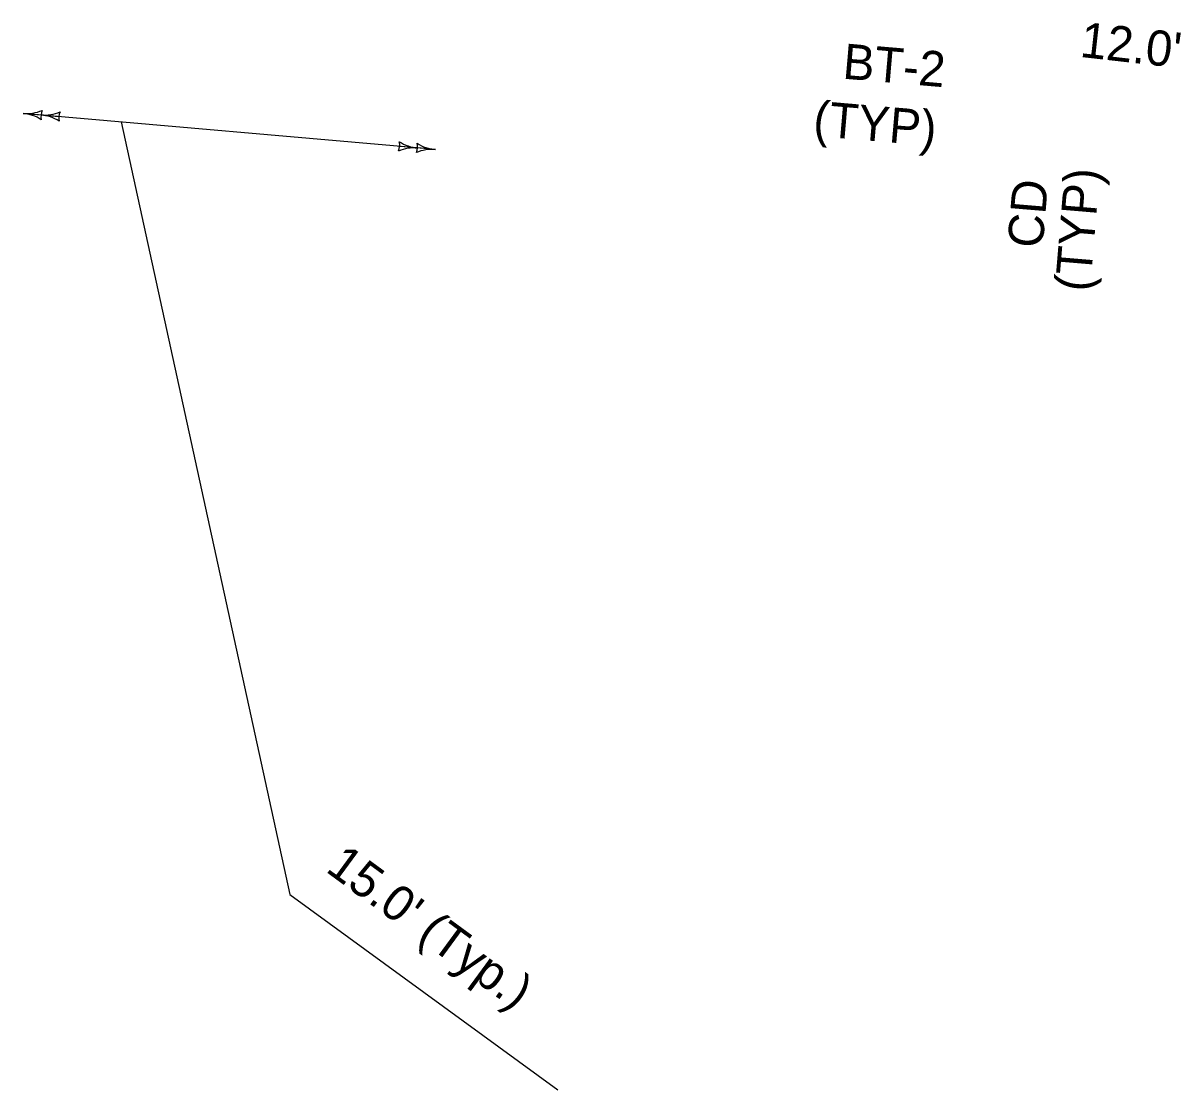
# Model space of a CAD drawing. Extents: x 15567221 to 15568484, y 8782768 to 8783889.
# Drawn here: x 15567891.2 to 15567953.3, y 8782767.6 to 8782824.8 of the extents above; entities that cross this region are included whole.
import ezdxf

# ---------------------------------------------------------------- set-up
doc = ezdxf.new("R2010")
doc.units = 0
for name, color, linetype in [('Default', 7, 'Continuous'), ('Drainage', 7, 'Continuous'), ('EXT_GU', 7, 'Continuous')]:
    doc.layers.add(name, color=color, linetype=linetype)

msp = doc.modelspace()

# ---------------------------------------------------------------- linework, layer by layer
at = {"layer": 'Drainage'}
for p, q in [((15567913.327, 8782817.986), (15567891.234, 8782819.924)), ((15567896.482, 8782819.464), (15567905.529, 8782778.036)), ((15567905.529, 8782778.036), (15567919.884, 8782767.57))]:
    msp.add_line(p, q, dxfattribs=at)
at = {"layer": 'EXT_GU'}
for p, q in [((15567891.234, 8782819.924), (15567891.717, 8782819.882)), ((15567891.234, 8782819.924), (15567892.191, 8782819.84)), ((15567892.191, 8782819.84), (15567892.674, 8782819.798)), ((15567892.191, 8782819.84), (15567893.149, 8782819.756)), ((15567912.369, 8782818.07), (15567911.412, 8782818.154)), ((15567912.369, 8782818.07), (15567911.887, 8782818.113)), ((15567913.327, 8782817.986), (15567912.369, 8782818.07)), ((15567913.327, 8782817.986), (15567912.844, 8782818.029))]:
    msp.add_line(p, q, dxfattribs=at)
for centre, radius, start, end in [((15567891.42, 8782822.041), 2.125, 264.98723, 293.05972), ((15567891.048, 8782817.807), 2.125, 56.91474, 84.98723), ((15567893.009, 8782819.768), 0.821, 157.25388, 192.72058), ((15567892.377, 8782821.957), 2.125, 264.98723, 293.05972), ((15567893.966, 8782819.684), 0.821, 157.25388, 192.72058), ((15567892.006, 8782817.723), 2.125, 56.91474, 84.98723), ((15567910.594, 8782818.226), 0.821, 337.25389, 12.72059), ((15567912.184, 8782815.953), 2.125, 84.98724, 113.05973), ((15567912.555, 8782820.187), 2.125, 236.91475, 264.98724), ((15567911.552, 8782818.142), 0.821, 337.25389, 12.72059), ((15567913.512, 8782820.103), 2.125, 236.91475, 264.98724), ((15567913.141, 8782815.869), 2.125, 84.98724, 113.05973)]:
    msp.add_arc(centre, radius, start, end, dxfattribs=at)

# ---------------------------------------------------------------- texts
at = {"layer": 'Default'}
for s, height, rotation, p in [("12.0'", 1.8898, 353.56721, (15567947.827, 8782822.959)), ('BT-2', 1.8898, 355.119, (15567935.114, 8782821.793)), ('(TYP)', 1.8898, 355.119, (15567933.532, 8782818.723)), ('(TYP)', 1.8898, 85.2197, (15567948.404, 8782810.337)), ('CD', 1.8898, 85.2197, (15567945.866, 8782812.662)), ("15.0' (Typ.)", 1.88976, 323.73637, (15567907.384, 8782779.315))]:
    msp.add_text(s, height=height, rotation=rotation, dxfattribs=at).set_placement(p)

doc.saveas('drawing.dxf')
